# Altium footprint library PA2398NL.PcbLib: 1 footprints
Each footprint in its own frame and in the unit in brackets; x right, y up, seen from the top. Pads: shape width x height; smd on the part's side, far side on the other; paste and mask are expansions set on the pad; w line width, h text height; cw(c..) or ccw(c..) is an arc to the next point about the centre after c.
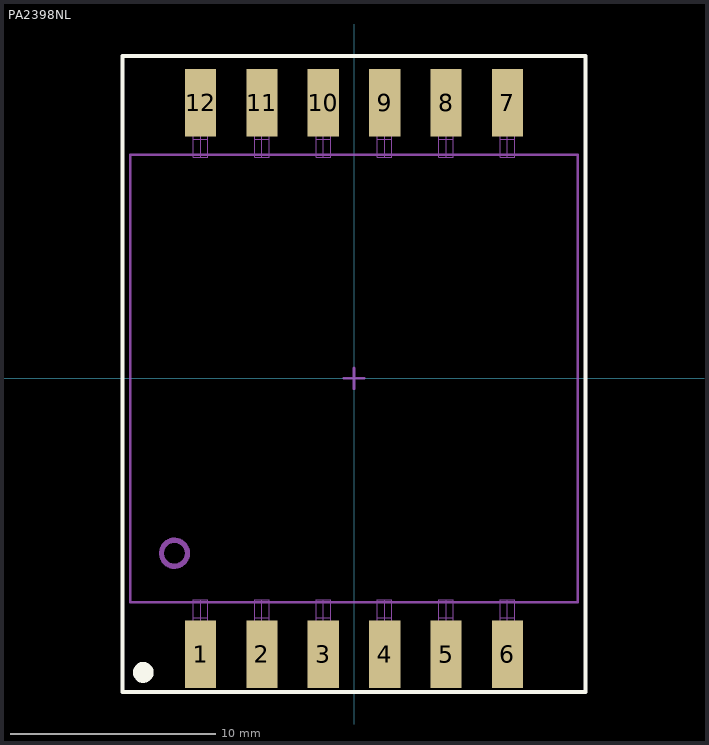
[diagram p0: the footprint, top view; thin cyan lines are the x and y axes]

## PA2398NL [mil] "Transformer"
height 450
pads (12):
  rect 60x130 smd: 1(-295,-530) 2(-177,-530) 3(-59,-530) 4(59,-530) 5(177,-530) 6(295,-530) 7(295,530) 8(177,530) 9(59,530) 10(-59,530) 11(-177,530) 12(-295,530)
Top Overlay:
  circle w20: c-405,-565 r10
  lines w7.78: -445,-603 -445,620 445,620 445,-603 -445,-603
M5 Assembly Top:
  drawing of 269 lines, arcs and shapes, not listed
  text ".Designator" at -198,-15 h40
M15  Courtyards Top:
  lines w5: -20,0 0,0 ; 0,-20 0,0 ; 0,20 0,0 ; 20,0 0,0
3D body: height 10, standoff 0, extent -309,495 -281,575
3D body: height 40, standoff 0, extent -309,495 -281,505
3D body: height 50, standoff 40, extent -309,425 -281,505
3D body: height 10, standoff 0, extent -191,495 -163,575
3D body: height 40, standoff 0, extent -191,495 -163,505
3D body: height 50, standoff 40, extent -191,425 -163,505
3D body: height 10, standoff 0, extent -73,495 -45,575
3D body: height 40, standoff 0, extent -73,495 -45,505
3D body: height 50, standoff 40, extent -73,425 -45,505
3D body: height 10, standoff 0, extent 45,495 73,575
3D body: height 40, standoff 0, extent 45,495 73,505
3D body: height 50, standoff 40, extent 45,425 73,505
3D body: height 10, standoff 0, extent 163,495 191,575
3D body: height 40, standoff 0, extent 163,495 191,505
3D body: height 50, standoff 40, extent 163,425 191,505
3D body: height 10, standoff 0, extent 281,495 309,575
3D body: height 40, standoff 0, extent 281,495 309,505
3D body: height 50, standoff 40, extent 281,425 309,505
3D body: height 10, standoff 0, extent 281,-575 309,-495
3D body: height 40, standoff 0, extent 281,-505 309,-495
3D body: height 50, standoff 40, extent 281,-505 309,-425
3D body: height 10, standoff 0, extent 163,-575 191,-495
3D body: height 40, standoff 0, extent 163,-505 191,-495
3D body: height 50, standoff 40, extent 163,-505 191,-425
3D body: height 10, standoff 0, extent 45,-575 73,-495
3D body: height 40, standoff 0, extent 45,-505 73,-495
3D body: height 50, standoff 40, extent 45,-505 73,-425
3D body: height 10, standoff 0, extent -73,-575 -45,-495
3D body: height 40, standoff 0, extent -73,-505 -45,-495
3D body: height 50, standoff 40, extent -73,-505 -45,-425
3D body: height 10, standoff 0, extent -191,-575 -163,-495
3D body: height 40, standoff 0, extent -191,-505 -163,-495
3D body: height 50, standoff 40, extent -191,-505 -163,-425
3D body: height 50, standoff 40, extent -309,-505 -281,-425
3D body: height 40, standoff 0, extent -309,-505 -281,-495
3D body: height 10, standoff 0, extent -309,-575 -281,-495
3D body: height 450.1, standoff 448, extent -369.8,-359.95 -320,-310.05
3D body: height 450, standoff 449, extent -430,-430 430,430
3D body: height 449, standoff 100, extent -430,-430 430,430
3D body: height 449.61, standoff 50.39, extent -425,-400 -26.58,400
3D body: height 449.61, standoff 50.39, extent 26.58,-400 425,400
3D body: height 200, standoff 50, extent -225.79,-400 225.79,400
3D body: height 90, standoff 10, extent -430,-430 430,-280
3D body: height 90, standoff 10, extent -430,280 430,430
3D body: height 110, standoff 80, extent -405,-320 405,-280
3D body: height 110, standoff 80, extent -405,280 405,320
